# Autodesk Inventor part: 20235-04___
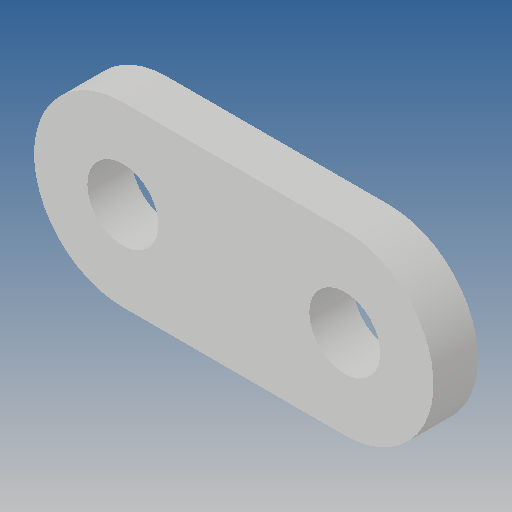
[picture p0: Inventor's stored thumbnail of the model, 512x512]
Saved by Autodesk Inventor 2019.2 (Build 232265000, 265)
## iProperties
Created: 2010-06
Part Number: 20235-04___
Material: Ogólny
Document SubType Name: Modeling
Designer: CADENGINEERING4
Density: 1 g/cm^3
Appearance: Domyślna
Author: CADENGINEERING4
Revision Number: ANY
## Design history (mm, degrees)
feature "NONE"
node "Bryła1"
